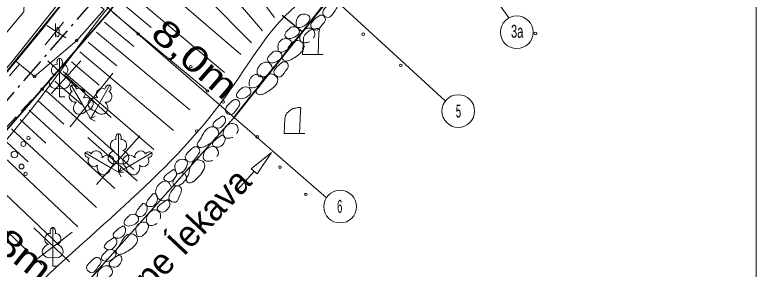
# Model space of a CAD drawing. Extents: x -1271.1 to -1218.8, y 769 to 838.3.
# Drawn here: x -1247.62 to -1218.85, y 808.82 to 818.71 of the extents above; entities that cross this region are included whole.
import ezdxf
from ezdxf.enums import TextEntityAlignment as Align

# ---------------------------------------------------------------- set-up
doc = ezdxf.new("R2010")
doc.units = 0
doc.header["$LTSCALE"] = 0.2
doc.linetypes.add('DOT_DASHED', pattern=[7.7, 5, -1.2, 0.3, -1.2])
doc.linetypes.add('MEDIUM_DASHED', pattern=[4.5, 3, -1.5])
for name, color, linetype, lineweight in [('1', 7, 'Continuous', 13), ('19', 7, 'Continuous', 13), ('35', 7, 'Continuous', 25), ('4', 7, 'Continuous', 13), ('5', 7, 'Continuous', 13), ('55', 7, 'Continuous', 13), ('56', 7, 'Continuous', 13), ('6', 7, 'Continuous', 13), ('61', 7, 'Continuous', 13), ('63', 7, 'Continuous', 13)]:
    doc.layers.add(name, color=color, linetype=linetype, lineweight=lineweight)
doc.layers.add('15', color=7, linetype='Continuous')
doc.layers.add('27', color=7, linetype='Continuous')

msp = doc.modelspace()

# ---------------------------------------------------------------- linework, layer by layer
at = {"layer": '1'}
for p, q in [((-1228.446, 818.593), (-1236.594, 830.173)), ((-1241.586, 825.164), (-1230.918, 815.373)), ((-1240.377, 822.41), (-1237.544, 818.612)), ((-1247.111, 821.685), (-1235.538, 811.611)), ((-1241.164, 821.793), (-1238.014, 818.09)), ((-1241.871, 821.088), (-1238.432, 817.627)), ((-1242.53, 820.335), (-1238.852, 817.164)), ((-1243.178, 819.573), (-1239.485, 816.469)), ((-1243.499, 819.19), (-1242.327, 818.215)), ((-1243.818, 818.805), (-1240.142, 815.757)), ((-1244.137, 818.42), (-1242.998, 817.476)), ((-1244.456, 818.036), (-1240.825, 815.021)), ((-1244.776, 817.651), (-1243.669, 816.729)), ((-1245.097, 817.268), (-1241.468, 814.213)), ((-1245.419, 816.885), (-1244.345, 815.976)), ((-1245.744, 816.505), (-1242.224, 813.478)), ((-1246.072, 816.127), (-1245.032, 815.219)), ((-1246.402, 815.753), (-1242.999, 812.703)), ((-1246.737, 815.381), (-1245.727, 814.465)), ((-1247.074, 815.011), (-1243.736, 811.955)), ((-1247.412, 814.643), (-1246.417, 813.726)), ((-1247.751, 814.276), (-1244.455, 811.216)), ((-1248.092, 813.91), (-1247.108, 812.991)), ((-1248.434, 813.546), (-1245.172, 810.47)), ((-1249.122, 812.819), (-1245.881, 809.729)), ((-1249.813, 812.097), (-1246.578, 808.992))]:
    msp.add_line(p, q, dxfattribs=at)
for centre in [(-1228.1385, 818.033), (-1230.4095, 814.972), (-1234.9969, 811.255)]:
    msp.add_circle(centre, 0.635, dxfattribs=at)
msp.add_spline([(-1235.8, 825.801), (-1237.913, 825.174), (-1239.203, 823.346), (-1241.709, 821.268), (-1246.557, 815.58), (-1256.526, 805.053), (-1260.592, 799.147), (-1261.416, 795.29), (-1262.742, 791.444), (-1262.206, 785.139)], degree=3, dxfattribs=at)
at = {"layer": '19'}
msp.add_spline([(-1253.457, 785.393), (-1253.726, 794.104), (-1251.637, 801.373), (-1250.122, 804.26), (-1247.608, 807.348), (-1239.437, 815.545), (-1236.508, 819.221), (-1228.799, 821.851), (-1223.357, 826.161), (-1220.079, 827.95)], degree=3, dxfattribs=at)
at = {"layer": '35'}
msp.add_lwpolyline([(-1264.692, 791.666), (-1263.121, 794.463), (-1262.995, 800.82), (-1256.407, 807.512), (-1249.819, 814.203), (-1245.888, 819.015), (-1242.275, 823.687), (-1240.604, 825.846), (-1237.968, 829.25), (-1236.511, 829.583), (-1228.03, 831.521)], dxfattribs=at)
at = {"layer": '35', "lineweight": 35}
msp.add_lwpolyline([(-1225.362, 830.487), (-1237.056, 827.834), (-1243.981, 818.809), (-1250.833, 810.905), (-1258.147, 803.474), (-1260.339, 800.099), (-1261.472, 796.156), (-1261.529, 794.093), (-1263.29, 790.894)], dxfattribs=at)
at = {"layer": '4'}
msp.add_line((-1239.008, 811.886), (-1238.334, 812.625), dxfattribs=at)
for points in [[(-1237.661, 813.364), (-1238.223, 812.524), (-1238.445, 812.726)], [(-1238.334, 812.625), (-1238.223, 812.524), (-1237.661, 813.364), (-1238.445, 812.726)]]:
    msp.add_lwpolyline(points, close=True, dxfattribs=at)
at = {"layer": '5'}
for p, q in [((-1235.855, 817.167), (-1235.821, 818.032)), ((-1235.855, 817.167), (-1236.455, 817.167)), ((-1235.855, 817.167), (-1235.655, 817.167)), ((-1245.884, 817.019), (-1245.884, 815.866)), ((-1245.794, 816.787), (-1245.795, 816.788)), ((-1245.432, 815.973), (-1244.856, 814.975)), ((-1243.932, 815.973), (-1244.509, 814.975)), ((-1245.884, 815.866), (-1245.884, 815.519)), ((-1245.238, 815.817), (-1245.24, 815.817)), ((-1243.971, 815.727), (-1243.971, 815.728)), ((-1245.884, 815.519), (-1245.684, 815.519)), ((-1244.856, 814.975), (-1244.682, 814.674)), ((-1244.509, 814.975), (-1244.682, 814.674)), ((-1244.682, 814.674), (-1244.509, 814.774)), ((-1236.571, 814.1), (-1236.537, 814.965)), ((-1244.682, 814.674), (-1244.509, 814.574)), ((-1243.601, 814.091), (-1243.601, 812.938)), ((-1236.571, 814.1), (-1237.171, 814.1)), ((-1236.571, 814.1), (-1236.371, 814.1)), ((-1243.511, 813.859), (-1243.512, 813.86)), ((-1244.9, 813.341), (-1243.902, 812.765)), ((-1244.654, 813.303), (-1244.655, 813.302)), ((-1242.302, 813.341), (-1243.301, 812.765)), ((-1242.458, 813.147), (-1242.458, 813.149)), ((-1243.902, 812.765), (-1243.601, 812.591)), ((-1243.601, 812.938), (-1243.601, 812.591)), ((-1243.301, 812.765), (-1243.601, 812.591)), ((-1243.601, 812.591), (-1243.501, 812.764)), ((-1243.601, 812.591), (-1243.401, 812.591)), ((-1243.601, 812.591), (-1243.501, 812.418)), ((-1246.152, 810.444), (-1246.152, 809.291)), ((-1246.062, 810.212), (-1246.063, 810.213)), ((-1246.152, 809.291), (-1246.152, 808.944)), ((-1246.152, 808.944), (-1245.952, 808.944))]:
    msp.add_line(p, q, dxfattribs=at)
for points in [[(-1236.424, 817.74), (-1236.455, 817.167), (-1236.155, 817.167), (-1235.855, 817.167)], [(-1237.14, 814.673), (-1237.171, 814.1), (-1236.871, 814.1), (-1236.571, 814.1)]]:
    msp.add_lwpolyline(points, dxfattribs=at)
for centre, radius in [((-1247.098, 813.9225), 0.064), ((-1247.2945, 813.6908), 0.096), ((-1247.642, 813.2832), 0.128), ((-1247.3656, 812.8163), 0.096), ((-1247.2081, 812.527), 0.064)]:
    msp.add_circle(centre, radius, dxfattribs=at)
for centre, major_axis, ratio, start_param, end_param in [((-1246.0123, 816.5744), (-0.0387, -0.2124), 0.861323, 3.1415927, 6.2831853), ((-1245.8836, 816.8692), (0, -0.1499), 0.707107, 3.1453698, 5.2874846), ((-1245.8845, 816.8692), (0, -0.1499), 0.707107, 0.9957007, 3.1378155), ((-1245.7558, 816.5744), (0.0387, -0.2124), 0.861323, 6.2831853, 9.424778), ((-1245.9736, 816.1121), (0.3068, 0.0951), 0.814445, 1.5707963, 4.7520146), ((-1245.7945, 816.1121), (-0.3068, 0.0951), 0.814445, 1.5311707, 4.712389), ((-1245.3567, 815.8435), (0.075, -0.1298), 0.707107, 3.1453698, 5.2874846), ((-1245.3574, 815.8431), (0.075, -0.1298), 0.707107, 0.9957007, 3.1378155), ((-1244.0067, 815.8431), (-0.075, -0.1298), 0.707107, 3.1453698, 5.2874846), ((-1244.0074, 815.8435), (-0.075, -0.1298), 0.707107, 0.9957007, 3.1378155), ((-1245.3208, 815.5238), (0.0727, -0.2033), 0.861323, 3.1415927, 6.2831853), ((-1245.0985, 815.6521), (0.1397, -0.1646), 0.861323, 6.2831853, 9.424778), ((-1244.2656, 815.6521), (-0.1397, -0.1646), 0.861323, 3.1415927, 6.2831853), ((-1244.0433, 815.5238), (-0.0727, -0.2033), 0.861323, 6.2831853, 9.424778), ((-1245.0561, 815.1428), (0.2182, 0.2358), 0.814445, 1.5707963, 4.7520146), ((-1244.9009, 815.2324), (-0.3133, -0.071), 0.814445, 1.5311707, 4.712389), ((-1244.4632, 815.2324), (0.3133, -0.071), 0.814445, 1.5707963, 4.7520146), ((-1244.308, 815.1428), (-0.2182, 0.2358), 0.814445, 1.5311707, 4.712389), ((-1243.6006, 813.9412), (0, -0.1499), 0.707107, 3.1453698, 5.2874846), ((-1243.6015, 813.9412), (0, -0.1499), 0.707107, 0.9957007, 3.1378155), ((-1243.7293, 813.6464), (-0.0387, -0.2124), 0.861323, 3.1415927, 6.2831853), ((-1243.4728, 813.6464), (0.0387, -0.2124), 0.861323, 6.2831853, 9.424778), ((-1244.77, 813.2665), (0.1298, -0.075), 0.707107, 3.1453698, 5.2874846), ((-1244.7704, 813.2658), (0.1298, -0.075), 0.707107, 0.9957007, 3.1378155), ((-1244.4507, 813.2299), (0.2033, -0.0727), 0.861323, 6.2831853, 9.424778), ((-1243.6906, 813.1841), (0.3068, 0.0951), 0.814445, 1.5707963, 4.7520146), ((-1243.5115, 813.1841), (-0.3068, 0.0951), 0.814445, 1.5311707, 4.712389), ((-1242.7514, 813.2299), (-0.2033, -0.0727), 0.861323, 3.1415927, 6.2831853), ((-1242.4317, 813.2658), (-0.1298, -0.075), 0.707107, 3.1453698, 5.2874846), ((-1242.4321, 813.2665), (-0.1298, -0.075), 0.707107, 0.9957007, 3.1378155), ((-1244.579, 813.0076), (0.1646, -0.1397), 0.861323, 3.1415927, 6.2831853), ((-1244.0697, 812.9652), (-0.2358, -0.2182), 0.814445, 1.5311707, 4.712389), ((-1243.1324, 812.9652), (0.2358, -0.2182), 0.814445, 1.5707963, 4.7520146), ((-1242.6231, 813.0076), (-0.1646, -0.1397), 0.861323, 6.2831853, 9.424778), ((-1244.1593, 812.81), (0.071, 0.3133), 0.814445, 1.5707963, 4.7520146), ((-1243.0428, 812.81), (-0.071, 0.3133), 0.814445, 1.5311707, 4.712389), ((-1246.1516, 810.2942), (0, -0.1499), 0.707107, 3.1453698, 5.2874846), ((-1246.1525, 810.2942), (0, -0.1499), 0.707107, 0.9957007, 3.1378155), ((-1246.2803, 809.9994), (-0.0387, -0.2124), 0.861323, 3.1415927, 6.2831853), ((-1246.0238, 809.9994), (0.0387, -0.2124), 0.861323, 6.2831853, 9.424778), ((-1246.2416, 809.5371), (0.3068, 0.0951), 0.814445, 1.5707963, 4.7520146), ((-1246.0625, 809.5371), (-0.3068, 0.0951), 0.814445, 1.5311707, 4.712389)]:
    msp.add_ellipse(centre, major_axis=major_axis, ratio=ratio, start_param=start_param, end_param=end_param, dxfattribs=at)
for points in [[(-1235.821, 818.032), (-1235.817, 818.063), (-1235.814, 818.074), (-1235.799, 818.136), (-1235.829, 818.171), (-1235.951, 818.165), (-1236.055, 818.147), (-1236.161, 818.108), (-1236.226, 818.064), (-1236.301, 818), (-1236.381, 817.902), (-1236.412, 817.813), (-1236.424, 817.739)], [(-1236.537, 814.965), (-1236.533, 814.996), (-1236.53, 815.007), (-1236.515, 815.069), (-1236.545, 815.104), (-1236.667, 815.098), (-1236.771, 815.08), (-1236.877, 815.041), (-1236.942, 814.997), (-1237.017, 814.933), (-1237.097, 814.835), (-1237.128, 814.746), (-1237.14, 814.672)]]:
    msp.add_spline(points, degree=3, dxfattribs=at)
at = {"layer": '55'}
msp.add_lwpolyline([(-1264.692, 791.666), (-1263.121, 794.463), (-1263.06, 799.299), (-1247.785, 816.834), (-1237.845, 829.32), (-1225.799, 831.912), (-1223.768, 834.184)], dxfattribs=at)
at = {"layer": '56'}
msp.add_lwpolyline([(-1247.583, 816.91), (-1246.86, 816.313), (-1245.222, 817.711), (-1244.154, 818.919), (-1245.261, 819.794)], close=True, dxfattribs=at)
at = {"layer": '6'}
for centre in [(-1242.833, 817.9632), (-1234.1, 817.959), (-1227.4119, 817.9836), (-1245.222, 817.7112), (-1232.6422, 816.7462), (-1240.792, 816.6942), (-1246.86, 816.3132), (-1246.564, 815.8232), (-1240.149, 815.7502), (-1239.537, 815.3252), (-1240.559, 814.1892), (-1238.212, 813.9701), (-1237.331, 812.7882), (-1236.323, 811.7341)]:
    msp.add_circle(centre, 0.05, dxfattribs=at)
at = {"layer": '61'}
msp.add_lwpolyline([(-1249.819, 814.203), (-1246.581, 818.124), (-1237.968, 829.25), (-1225.679, 832.058)], dxfattribs=at)
at = {"layer": '63'}
for p, q in [((-1218.845, 838.277), (-1218.845, 768.981)), ((-1245.74, 818.424), (-1246.449, 817.546)), ((-1246.381, 818.289), (-1245.638, 817.816)), ((-1246.349, 816.919), (-1245.234, 815.905)), ((-1245.065, 816.919), (-1246.214, 815.635)), ((-1245.538, 816.243), (-1243.882, 814.723)), ((-1243.815, 816.446), (-1245.47, 814.351)), ((-1244.795, 813.946), (-1242.869, 812.256)), ((-1242.767, 814.013), (-1244.457, 812.121)), ((-1246.889, 810.432), (-1245.504, 809.115)), ((-1246.991, 809.047), (-1245.403, 810.263))]:
    msp.add_line(p, q, dxfattribs=at)
at = {"layer": '63', "lineweight": 25}
msp.add_line((-1236.466, 818.053), (-1237.24, 818.685), dxfattribs=at)
at = {"layer": '63'}
msp.add_lwpolyline([(-1256.412, 818.123), (-1256.201, 815.29), (-1252.408, 813.098), (-1251.504, 813.774), (-1247.278, 818.829), (-1247.088, 823.447), (-1246.858, 826.564), (-1246.095, 828.381), (-1245.357, 829.125), (-1242.02, 832.546), (-1243.096, 833.394)], dxfattribs=at)
at = {"layer": '63', "linetype": 'MEDIUM_DASHED'}
for points in [[(-1265.079, 785.987), (-1263.807, 789.442), (-1261.536, 795.397), (-1260.86, 799.605), (-1256.627, 805.136), (-1246.564, 815.823), (-1241.769, 821.378), (-1239.214, 823.453), (-1237.177, 827.558), (-1234.848, 828.79), (-1231.517, 829.195), (-1224.557, 831.447)], [(-1247.437, 816.79), (-1257.209, 805.83), (-1262.318, 799.97), (-1262.654, 795.375), (-1263.503, 792.223), (-1265.015, 790.631), (-1268.643, 788.504)]]:
    msp.add_lwpolyline(points, dxfattribs=at)
at = {"layer": '63', "linetype": 'DOT_DASHED', "lineweight": 25}
for points in [[(-1225.528, 831.218), (-1237.486, 828.505), (-1244.562, 819.283), (-1251.384, 811.414), (-1258.735, 803.946), (-1261.029, 800.414), (-1262.219, 796.272), (-1262.274, 794.295), (-1264.33, 790.56), (-1266.742, 787.222)], [(-1254.918, 786.26), (-1254.605, 794.542), (-1253.865, 797.042), (-1252.437, 799.553), (-1250.698, 801.658), (-1245.95, 807.041), (-1239.139, 814.697), (-1235.363, 819.429), (-1232.239, 822.444), (-1231.619, 822.931), (-1231.44, 822.991), (-1229.31, 823.677), (-1223.125, 826.536)]]:
    msp.add_lwpolyline(points, dxfattribs=at)
at = {"layer": '63', "lineweight": 35}
msp.add_lwpolyline([(-1254.918, 786.26), (-1254.605, 794.542), (-1253.865, 797.042), (-1252.437, 799.553), (-1251.568, 800.606), (-1250.698, 801.658), (-1248.324, 804.35), (-1245.95, 807.041), (-1242.544, 810.869), (-1239.139, 814.697), (-1237.251, 817.063), (-1235.363, 819.429), (-1233.801, 820.936), (-1232.239, 822.444), (-1231.619, 822.931), (-1229.31, 823.677), (-1223.125, 826.536)], dxfattribs=at)
at = {"layer": '63'}
for points in [[(-1235.32, 819.205), (-1235.54, 819.02), (-1235.667, 818.751), (-1235.461, 818.608), (-1235.217, 818.844), (-1235.112, 819.038), (-1235.193, 819.185), (-1235.32, 819.205)], [(-1236.692, 818.294), (-1236.676, 818.547), (-1236.519, 818.717), (-1236.278, 818.712), (-1236.175, 818.616), (-1236.255, 818.399), (-1236.39, 818.28), (-1236.613, 818.221), (-1236.69, 818.245)], [(-1235.77, 818.703), (-1235.998, 818.528), (-1236.137, 818.265), (-1235.937, 818.113), (-1235.683, 818.338), (-1235.569, 818.527), (-1235.644, 818.678), (-1235.77, 818.703)], [(-1236.926, 818.226), (-1236.648, 818.211), (-1236.578, 818.05), (-1236.773, 817.842), (-1237.047, 817.806), (-1237.139, 817.89), (-1237.045, 818.095), (-1236.911, 818.213)], [(-1236.033, 817.799), (-1235.975, 817.965), (-1236.135, 818.186), (-1236.373, 818.139), (-1236.54, 817.932), (-1236.519, 817.667), (-1236.341, 817.624), (-1236.19, 817.655)], [(-1237.402, 817.338), (-1237.386, 817.591), (-1237.229, 817.761), (-1236.988, 817.756), (-1236.885, 817.66), (-1236.965, 817.443), (-1237.1, 817.324), (-1237.323, 817.265), (-1237.4, 817.289)], [(-1236.999, 816.935), (-1237.137, 816.917), (-1237.228, 817.002), (-1237.122, 817.218), (-1236.969, 817.49), (-1236.637, 817.717), (-1236.405, 817.548), (-1236.665, 817.111), (-1236.887, 816.977), (-1236.986, 816.922)], [(-1237.606, 817.28), (-1237.328, 817.265), (-1237.258, 817.104), (-1237.453, 816.896), (-1237.727, 816.86), (-1237.819, 816.944), (-1237.725, 817.149), (-1237.591, 817.267)], [(-1237.691, 816.474), (-1237.633, 816.64), (-1237.793, 816.861), (-1238.031, 816.814), (-1238.198, 816.607), (-1238.177, 816.342), (-1237.999, 816.299), (-1237.848, 816.33)], [(-1237.216, 816.889), (-1237.436, 816.704), (-1237.563, 816.435), (-1237.357, 816.292), (-1237.113, 816.528), (-1237.008, 816.722), (-1237.089, 816.869), (-1237.216, 816.889)], [(-1238.519, 815.945), (-1238.503, 816.198), (-1238.346, 816.368), (-1238.105, 816.363), (-1238.002, 816.267), (-1238.082, 816.05), (-1238.217, 815.931), (-1238.44, 815.872), (-1238.517, 815.896)], [(-1238.02, 815.629), (-1238.158, 815.611), (-1238.249, 815.696), (-1238.143, 815.912), (-1237.99, 816.184), (-1237.658, 816.411), (-1237.426, 816.242), (-1237.686, 815.805), (-1237.908, 815.671), (-1238.007, 815.616)], [(-1238.806, 815.887), (-1238.528, 815.872), (-1238.458, 815.711), (-1238.653, 815.503), (-1238.927, 815.467), (-1239.019, 815.551), (-1238.925, 815.756), (-1238.791, 815.874)], [(-1239.101, 815.42), (-1239.321, 815.235), (-1239.448, 814.966), (-1239.242, 814.823), (-1238.998, 815.059), (-1238.893, 815.253), (-1238.974, 815.4), (-1239.101, 815.42)], [(-1239.557, 814.786), (-1239.766, 814.643), (-1239.934, 814.408), (-1239.716, 814.308), (-1239.532, 814.417), (-1239.448, 814.652), (-1239.523, 814.769), (-1239.582, 814.769)], [(-1239.009, 814.091), (-1238.951, 814.257), (-1239.111, 814.478), (-1239.349, 814.431), (-1239.516, 814.224), (-1239.495, 813.959), (-1239.317, 813.916), (-1239.166, 813.947)], [(-1240.316, 813.575), (-1240.454, 813.557), (-1240.545, 813.642), (-1240.439, 813.858), (-1240.286, 814.13), (-1239.954, 814.357), (-1239.722, 814.188), (-1239.982, 813.751), (-1240.204, 813.617), (-1240.303, 813.562)], [(-1239.572, 814.042), (-1239.781, 813.899), (-1239.949, 813.664), (-1239.731, 813.564), (-1239.547, 813.673), (-1239.463, 813.908), (-1239.538, 814.025), (-1239.597, 814.025)], [(-1239.777, 813.196), (-1239.719, 813.362), (-1239.879, 813.583), (-1240.117, 813.536), (-1240.284, 813.329), (-1240.263, 813.064), (-1240.085, 813.021), (-1239.934, 813.052)], [(-1240.655, 813.582), (-1240.875, 813.397), (-1241.002, 813.128), (-1240.796, 812.985), (-1240.552, 813.221), (-1240.447, 813.415), (-1240.528, 813.562), (-1240.655, 813.582)], [(-1241.364, 812.584), (-1241.411, 812.834), (-1241.3, 813.037), (-1241.065, 813.091), (-1240.942, 813.023), (-1240.966, 812.793), (-1241.068, 812.645), (-1241.27, 812.533), (-1241.35, 812.537)], [(-1240.712, 812.227), (-1240.842, 812.176), (-1240.951, 812.236), (-1240.901, 812.472), (-1240.819, 812.773), (-1240.553, 813.074), (-1240.286, 812.967), (-1240.432, 812.48), (-1240.614, 812.296), (-1240.697, 812.218)], [(-1241.46, 812.699), (-1241.669, 812.556), (-1241.837, 812.321), (-1241.619, 812.221), (-1241.435, 812.33), (-1241.351, 812.565), (-1241.426, 812.682), (-1241.485, 812.682)], [(-1241.346, 812.506), (-1241.073, 812.56), (-1240.966, 812.421), (-1241.104, 812.171), (-1241.361, 812.069), (-1241.471, 812.128), (-1241.43, 812.35), (-1241.329, 812.497)], [(-1241.543, 812.004), (-1241.719, 812.242), (-1242.025, 812.125), (-1242.144, 811.724), (-1241.945, 811.492), (-1241.633, 811.545)], [(-1241.397, 812.046), (-1241.565, 811.813), (-1241.623, 811.521), (-1241.388, 811.433), (-1241.209, 811.721), (-1241.155, 811.935), (-1241.269, 812.058), (-1241.397, 812.046)], [(-1242.238, 811.769), (-1242.406, 811.579), (-1242.511, 811.31), (-1242.276, 811.267), (-1242.124, 811.417), (-1242.1, 811.666), (-1242.201, 811.761), (-1242.258, 811.746)], [(-1242.643, 811.386), (-1242.81, 811.196), (-1242.916, 810.927), (-1242.68, 810.884), (-1242.528, 811.035), (-1242.504, 811.283), (-1242.606, 811.378), (-1242.663, 811.364)], [(-1241.719, 811.522), (-1241.928, 811.379), (-1242.096, 811.144), (-1241.878, 811.044), (-1241.694, 811.153), (-1241.61, 811.388), (-1241.685, 811.505), (-1241.744, 811.505)], [(-1241.984, 810.782), (-1241.969, 810.958), (-1242.178, 811.133), (-1242.397, 811.029), (-1242.508, 810.787), (-1242.423, 810.536), (-1242.24, 810.537), (-1242.101, 810.604)], [(-1243.168, 810.937), (-1242.89, 810.922), (-1242.82, 810.761), (-1243.015, 810.553), (-1243.289, 810.517), (-1243.381, 810.601), (-1243.287, 810.806), (-1243.153, 810.924)], [(-1243.432, 810.507), (-1243.641, 810.364), (-1243.809, 810.129), (-1243.591, 810.029), (-1243.407, 810.138), (-1243.323, 810.373), (-1243.398, 810.49), (-1243.457, 810.49)], [(-1242.875, 810.14), (-1242.922, 810.389), (-1242.811, 810.592), (-1242.576, 810.646), (-1242.453, 810.578), (-1242.477, 810.348), (-1242.579, 810.2), (-1242.781, 810.088), (-1242.862, 810.093)], [(-1243.464, 809.422), (-1243.602, 809.404), (-1243.693, 809.489), (-1243.587, 809.705), (-1243.434, 809.977), (-1243.102, 810.204), (-1242.87, 810.035), (-1243.13, 809.598), (-1243.352, 809.464), (-1243.451, 809.409)], [(-1243.775, 810.058), (-1243.984, 809.915), (-1244.152, 809.68), (-1243.934, 809.58), (-1243.75, 809.689), (-1243.666, 809.924), (-1243.741, 810.041), (-1243.8, 810.041)], [(-1244.049, 809.563), (-1243.771, 809.548), (-1243.701, 809.387), (-1243.896, 809.179), (-1244.17, 809.143), (-1244.262, 809.227), (-1244.168, 809.432), (-1244.034, 809.55)], [(-1244.486, 809.285), (-1244.706, 809.1), (-1244.833, 808.831), (-1244.627, 808.688), (-1244.383, 808.924), (-1244.278, 809.118), (-1244.359, 809.265), (-1244.486, 809.285)], [(-1243.584, 809.377), (-1243.793, 809.234), (-1243.961, 808.999), (-1243.743, 808.899), (-1243.559, 809.008), (-1243.475, 809.243), (-1243.55, 809.36), (-1243.609, 809.36)], [(-1244.039, 808.449), (-1243.836, 808.728), (-1243.996, 808.949), (-1244.234, 808.902), (-1244.401, 808.695), (-1244.38, 808.43), (-1244.202, 808.387), (-1244.051, 808.418)]]:
    msp.add_spline(points, degree=3, dxfattribs=at)

# ---------------------------------------------------------------- texts
at = {"layer": '1'}
for s, width, p in [('3a', 0.65, (-1228.364, 817.819)), ('5', 0.55, (-1230.505, 814.716)), ('6', 0.55, (-1235.114, 811.016))]:
    msp.add_text(s, height=0.5, dxfattribs=dict(at, width=width)).set_placement(p)
at = {"layer": '15', "width": 0.6}
msp.add_text('b', height=0.5, dxfattribs=at).set_placement((-1246.087, 817.848))
at = {"layer": '27'}
msp.add_text('upe Íekava', height=1, rotation=46.796, dxfattribs=at).set_placement((-1242.855, 807.398))
at = {"layer": '63'}
for s, rotation, width, p in [('8,0m', 318.961, 1.3, (-1240.9548, 816.6143)), ('7,8m', 321.432, 1.25, (-1248.1252, 809.4158))]:
    msp.add_text(s, height=1, rotation=rotation, dxfattribs=dict(at, width=width)).set_placement(p, align=Align.CENTER)

doc.saveas('drawing.dxf')
